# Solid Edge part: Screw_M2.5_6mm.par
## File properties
Author: hhakima
Template: Normal.par
Last saved by: Houman
Revision: 8
Application: Solid Edge
Material: Stainless steel
Face Style: Steel
Fill Style: ANSI32(Steel)
Virtual Style: Stainless steel
Coef. of Thermal Exp: 1.6e-05
Thermal Conductivity: 17.0
Specific Heat: 502.0
Modulus of Elasticity: 193053196000.0
Poission's Ratio: 0.29
Yield Stress: 310264065.0
Ultimate Stress: 641212401.0
Elongation: 0.0
Density: 7750.000 kg/m^3
Accuracy: 0.990
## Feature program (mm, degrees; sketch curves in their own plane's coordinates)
body "unnamed Body 1"
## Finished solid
Body 1: solid body, 24 faces, 41 edges, 20 vertices.
  Faces by surface: plane 10, cone 9, cylinder 3, spline 2
  Edges by curve: circle 15, line 12, intersection 10, spline 4
Bounding box of the edges (mm; curved faces can reach further): 4.500 x 4.500 x 8.500, from (-2.25, -2.25, -8.5) to (2.25, 2.25, 0).
Cylindrical faces by radius (mm): R0.9577 x1, R1.25 x1, R2.25 x1
Conical faces (half-angle, radius in mm at the cone's reference point): 45 deg R1.1547 x6, 45 deg R2.025 x1, 45 deg R2.25 x1, 55 deg R0.7037 x1
Planar faces by outward normal: +x 1, +z 2, -x 1, -z 2, oblique 4
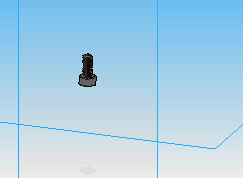
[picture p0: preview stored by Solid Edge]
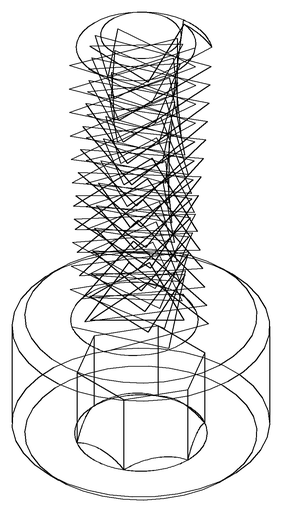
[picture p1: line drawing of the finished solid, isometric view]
